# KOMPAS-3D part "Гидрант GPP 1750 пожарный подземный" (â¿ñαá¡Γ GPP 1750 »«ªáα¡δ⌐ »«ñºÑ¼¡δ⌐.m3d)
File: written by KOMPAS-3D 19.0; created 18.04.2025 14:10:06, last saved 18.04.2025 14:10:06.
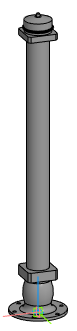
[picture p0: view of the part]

Document properties: Полное имя файла: E:\Dendor Работа Сачек\3D для проекитирвщиков\11.1 Тип GPP. Гидрант пожарный подземный\stp_Тип GPP. 750-6000 Гидрант пожарный подземный\Гидрант GPP 1750 пожарный подземный.m3d

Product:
- Part/product: Гидрант GPP 1750 пожарный подземный

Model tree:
1. Операция без истории:1  (labels: Гидрант GPP 1750 пожарный подземный)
